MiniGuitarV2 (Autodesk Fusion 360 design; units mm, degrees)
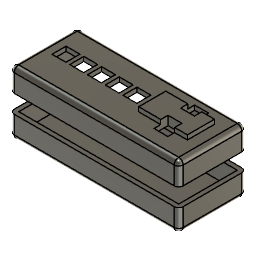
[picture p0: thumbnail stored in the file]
part number: 2026-03-30-15-54-44-268
sketch "Sketch1" plane through (0, 0, 0) normal (0, 0, 1) x axis (1, 0, 0)
  line L1 (127, 0) -> (-63.5, 0)
  line L2 (127, 76.2) -> (127, 0)
  line L3 (-63.5, 76.2) -> (127, 76.2)
  line L4 (-63.5, 0) -> (-63.5, 76.2)
  horizontal L1
  perpendicular L1 L2
  perpendicular L2 L3
  perpendicular L1 L4
extrude "Extrude1" new body sketch "Sketch1" along normal blind 50.8
sketch "Sketch2" plane through (0, 0, 0) normal (0, -1, 0) x axis (1, 0, 0)
  line L1 (127, 0) -> (-63.5, 0)
  line L2 (127, 50.8) -> (127, 0)
  line L3 (-63.5, 50.8) -> (127, 50.8)
  line L4 (-63.5, 0) -> (-63.5, 50.8)
  line L5 (114.3, 25.4) -> (-50.8, 25.4)
  horizontal L5
split "Split1"
move "Move1"
shell "Shell1" innerThickness 5.08
shell "Shell2" innerThickness 5.08
fillet "Fillet1" radius 5.08
sketch "Sketch3" plane through (0, 0, 71.12) normal (0, 0, 1) x axis (-1, 0, 0)
  line L1 (-121.92, -71.12) -> (-121.92, -5.08)
  line L2 (58.42, -71.12) -> (-121.92, -71.12)
  line L3 (58.42, -5.08) -> (58.42, -71.12)
  line L4 (-121.92, -5.08) -> (58.42, -5.08)
  line L5 (34.4, -50) -> (50, -50)
  line L6 (34.4, -34.2) -> (34.4, -50)
  line L7 (50, -34.2) -> (34.4, -34.2)
  line L8 (50, -50) -> (50, -34.2)
  line L9 (30, -34.2) -> (30, -50)
  line L10 (14.4, -34.2) -> (30, -34.2)
  line L11 (14.4, -50) -> (14.4, -34.2)
  line L12 (14.4, -50) -> (30, -50)
  point P6 (50, -50)
  point P7 (34.4, -50)
  point P8 (34.4, -34.2)
  point P10 (30, -50)
  point P11 (30, -34.2)
  point P12 (14.4, -34.2)
  horizontal L5
  perpendicular L5 L6
  perpendicular L3 L7
  perpendicular L5 L8
  perpendicular L7 L9
  perpendicular L8 L10
  perpendicular L5 L11
  perpendicular L11 L12
  dimension "d7" distance P6 P7 = 15.6
  dimension "d8" distance P7 P8 = 15.8
  dimension "d10" distance P10 P11 = 15.8
  dimension "d11" distance P11 P12 = 15.6
extrude "Extrude2" cut sketch "Sketch3" profile of L5 L6 L7 L8 L9 L10 L11 L12 against normal blind 10
sketch "Sketch4" plane through (0, 0, 71.12) normal (0, 0, 1) x axis (-1, 0, 0)
  line L1 (34.4, -34.2) -> (34.4, -50)
  line L2 (50, -34.2) -> (34.4, -34.2)
  line L3 (50, -50) -> (50, -34.2)
  line L4 (34.4, -50) -> (50, -50)
  line L5 (14.4, -34.2) -> (14.4, -50)
  line L6 (30, -34.2) -> (14.4, -34.2)
  line L7 (30, -50) -> (30, -34.2)
  line L8 (14.4, -50) -> (30, -50)
  line L9 (-121.92, -71.12) -> (-121.92, -5.08)
  line L10 (58.42, -71.12) -> (-121.92, -71.12)
  line L11 (58.42, -5.08) -> (58.42, -71.12)
  line L12 (-121.92, -5.08) -> (58.42, -5.08)
  line L13 (10, -34.2) -> (10, -50)
  line L14 (-5.6, -34.2) -> (10, -34.2)
  line L15 (-5.6, -50) -> (-5.6, -34.2)
  line L16 (10, -50) -> (-5.6, -50)
  line L17 (-10, -34.2) -> (-10, -50)
  line L18 (-25.6, -34.2) -> (-10, -34.2)
  line L19 (-25.6, -50) -> (-25.6, -34.2)
  line L20 (-10, -50) -> (-25.6, -50)
  line L21 (-30, -34.2) -> (-30, -50)
  line L22 (-45.6, -34.2) -> (-30, -34.2)
  line L23 (-45.6, -50) -> (-45.6, -34.2)
  line L24 (-30, -50) -> (-45.6, -50)
  point P14 (10, -50)
  point P15 (10, -34.2)
  point P16 (-5.6, -34.2)
  point P18 (-10, -50)
  point P19 (-10, -34.2)
  point P20 (-25.6, -34.2)
  point P22 (-30, -50)
  point P23 (-30, -34.2)
  point P24 (-45.6, -34.2)
  vertical L13
  perpendicular L13 L14
  perpendicular L14 L15
  perpendicular L13 L16
  perpendicular L16 L17
  perpendicular L13 L18
  perpendicular L18 L19
  perpendicular L17 L20
  perpendicular L18 L21
  perpendicular L17 L22
  perpendicular L18 L23
  perpendicular L21 L24
  dimension "d14" distance P14 P15 = 15.8
  dimension "d15" distance P15 P16 = 15.6
  dimension "d16" distance P18 P19 = 15.8
  dimension "d17" distance P19 P20 = 15.6
  dimension "d18" distance P22 P23 = 15.8
  dimension "d19" distance P23 P24 = 15.6
extrude "Extrude3" cut sketch "Sketch4" profile of L13 L14 L15 L16 L17 L18 L19 L20 L21 L22 L23 L24 against normal blind 10
sketch "Sketch5" plane through (0, 0, 71.12) normal (0, 0, 1) x axis (-1, 0, 0)
  line L1 (10, -50) -> (10, -34.2)
  line L2 (-5.6, -50) -> (10, -50)
  line L3 (-5.6, -34.2) -> (-5.6, -50)
  line L4 (10, -34.2) -> (-5.6, -34.2)
  line L5 (-10, -50) -> (-10, -34.2)
  line L6 (-25.6, -50) -> (-10, -50)
  line L7 (-25.6, -34.2) -> (-25.6, -50)
  line L8 (-10, -34.2) -> (-25.6, -34.2)
  line L9 (-30, -50) -> (-30, -34.2)
  line L10 (-45.6, -50) -> (-30, -50)
  line L11 (-45.6, -34.2) -> (-45.6, -50)
  line L12 (-30, -34.2) -> (-45.6, -34.2)
  line L13 (34.4, -34.2) -> (34.4, -50)
  line L14 (50, -34.2) -> (34.4, -34.2)
  line L15 (50, -50) -> (50, -34.2)
  line L16 (34.4, -50) -> (50, -50)
  line L17 (14.4, -34.2) -> (14.4, -50)
  line L18 (30, -34.2) -> (14.4, -34.2)
  line L19 (30, -50) -> (30, -34.2)
  line L20 (14.4, -50) -> (30, -50)
  line L21 (-121.92, -71.12) -> (-121.92, -5.08)
  line L22 (58.42, -71.12) -> (-121.92, -71.12)
  line L23 (58.42, -5.08) -> (58.42, -71.12)
  line L24 (-121.92, -5.08) -> (58.42, -5.08)
  line L25 (-80, -49.2) -> (-80, -65)
  line L26 (-95.6, -49.2) -> (-80, -49.2)
  line L27 (-95.6, -65) -> (-95.6, -49.2)
  line L28 (-80, -65) -> (-95.6, -65)
  line L29 (-80, -19.2) -> (-80, -35)
  line L30 (-95.6, -19.2) -> (-80, -19.2)
  line L31 (-95.6, -35) -> (-95.6, -19.2)
  line L32 (-80, -35) -> (-95.6, -35)
  point P26 (-80, -65)
  point P27 (-80, -49.2)
  point P28 (-95.6, -49.2)
  point P30 (-80, -35)
  point P31 (-80, -19.2)
  point P32 (-95.6, -19.2)
  perpendicular L22 L25
  perpendicular L25 L26
  perpendicular L22 L27
  perpendicular L25 L28
  vertical L29
  perpendicular L29 L30
  perpendicular L30 L31
  perpendicular L29 L32
  dimension "d22" distance P26 P27 = 15.8
  dimension "d23" distance P27 P28 = 15.6
  dimension "d24" distance P30 P31 = 15.8
  dimension "d25" distance P31 P32 = 15.6
extrude "Extrude4" cut sketch "Sketch5" profile of L16 L25 L26 L27 L28 L29 L30 L31 L32 against normal blind 5
extrude "Extrude5" cut of existing geometry blind -0.08
extrude "Extrude6" cut of existing geometry blind -15
sketch "Sketch6" plane through (0, 0, 71.12) normal (0, 0, 1) x axis (-1, 0, 0)
  line L1 (-80, -65) -> (-80, -49.2)
  line L2 (-95.6, -65) -> (-80, -65)
  line L3 (-95.6, -49.2) -> (-95.6, -65)
  line L4 (-80, -49.2) -> (-95.6, -49.2)
  line L5 (-80, -35) -> (-80, -19.2)
  line L6 (-95.6, -35) -> (-80, -35)
  line L7 (-95.6, -19.2) -> (-95.6, -35)
  line L8 (-80, -19.2) -> (-95.6, -19.2)
  line L9 (10, -50) -> (10, -34.2)
  line L10 (-5.6, -50) -> (10, -50)
  line L11 (-5.6, -34.2) -> (-5.6, -50)
  line L12 (10, -34.2) -> (-5.6, -34.2)
  line L13 (-10, -50) -> (-10, -34.2)
  line L14 (-25.6, -50) -> (-10, -50)
  line L15 (-25.6, -34.2) -> (-25.6, -50)
  line L16 (-10, -34.2) -> (-25.6, -34.2)
  line L17 (-30, -50) -> (-30, -34.2)
  line L18 (-45.6, -50) -> (-30, -50)
  line L19 (-45.6, -34.2) -> (-45.6, -50)
  line L20 (-30, -34.2) -> (-45.6, -34.2)
  line L21 (34.4, -34.2) -> (34.4, -50)
  line L22 (50, -34.2) -> (34.4, -34.2)
  line L23 (50, -50) -> (50, -34.2)
  line L24 (34.4, -50) -> (50, -50)
  line L25 (14.4, -34.2) -> (14.4, -50)
  line L26 (30, -34.2) -> (14.4, -34.2)
  line L27 (30, -50) -> (30, -34.2)
  line L28 (14.4, -50) -> (30, -50)
  line L29 (-121.92, -71.12) -> (-121.92, -5.08)
  line L30 (58.42, -71.12) -> (-121.92, -71.12)
  line L31 (58.42, -5.08) -> (58.42, -71.12)
  line L32 (-121.92, -5.08) -> (58.42, -5.08)
  line L33 (-55.1299, -26.8295) -> (-55.1299, -57.3614)
  line L34 (-110, -26.8295) -> (-55.1299, -26.8295)
  line L35 (-110, -57.3614) -> (-110, -26.8295)
  line L36 (-55.1299, -57.3614) -> (-110, -57.3614)
  vertical L33
  perpendicular L7 L34
  perpendicular L34 L35
  perpendicular L33 L36
extrude "Extrude7" add sketch "Sketch6" profile of L1 L3 L4 L5 L6 L7 L33 L34 L35 L36 along normal blind 5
